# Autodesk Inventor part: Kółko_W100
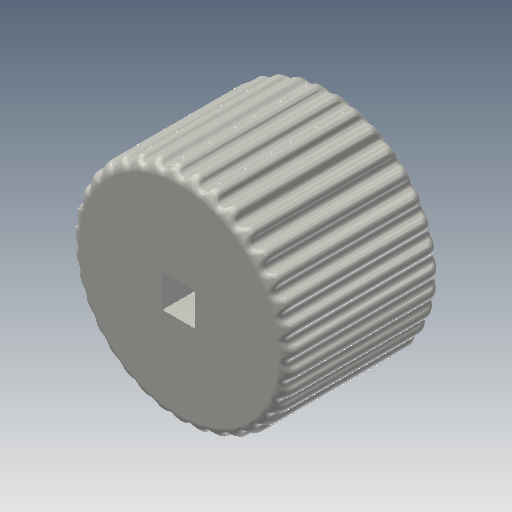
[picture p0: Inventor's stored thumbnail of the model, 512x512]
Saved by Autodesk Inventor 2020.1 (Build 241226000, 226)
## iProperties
Created: 2005-10
Part Number: Kółko_W100
Document SubType Name: Modeling
Designer: F.Stasiak
Density: 1 g/cm^3
Material: Ogólny
Appearance: Gładkie — w kolorze kości słoniowej
Manager: www.cadconsulting.pl
Company: Fabian Stasiak CAD Consulting
Author: F.Stasiak
Subject: Zbiór ćwiczeń. Autodesk Inventor 2020. Kurs podstawowy
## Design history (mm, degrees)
sketch "Szkic1"
  geometry: L1 (0, 6)-(-6, 6); L2 (-6, 6)-(-6, 0); L3 (-6, 0)-(0, 0); L4 (0, 0)-(0, 6); C1 r 3 at (-3, 3) reference; C2 r 20 at (-3, 3)
  constraints: 8 end point, 2 parallel, 1 centre point, 1 coincident, 1 horizontal, 1 perpendicular, 2 other
  dimensions: "d0" = 40 diameter of C2
extrude "Wyciągnięcie proste1" new body sketch "Szkic1" stored distance "d1" = 28; taper "d2" = 0 deg
fillet "Zaokrąglenie1" dims "d3" = 2
sketch "Szkic2"
  geometry: L1 (0, 0)-(0, 20); C1 r 1 at (0, 20)
  constraints: 2 end point, 1 centre point, 1 coincident, 1 vertical, 1 vertical alignment, 1 other
  dimensions: "d4" = 2 diameter of C1
extrude "Wyciągnięcie proste2" cut sketch "Szkic2" extent not by distance; stored distance "d5" = 30; taper "d6" = 0 deg
fillet "Zaokrąglenie2" dims "d7" = 1
node "Bryła1"
node "Korpusy bryłowe"
node "Korpusy powierzchniowe"
pattern_circular "Szyk kołowy1" dims angle "d9" = 360 deg
node "Odniesienie1"
